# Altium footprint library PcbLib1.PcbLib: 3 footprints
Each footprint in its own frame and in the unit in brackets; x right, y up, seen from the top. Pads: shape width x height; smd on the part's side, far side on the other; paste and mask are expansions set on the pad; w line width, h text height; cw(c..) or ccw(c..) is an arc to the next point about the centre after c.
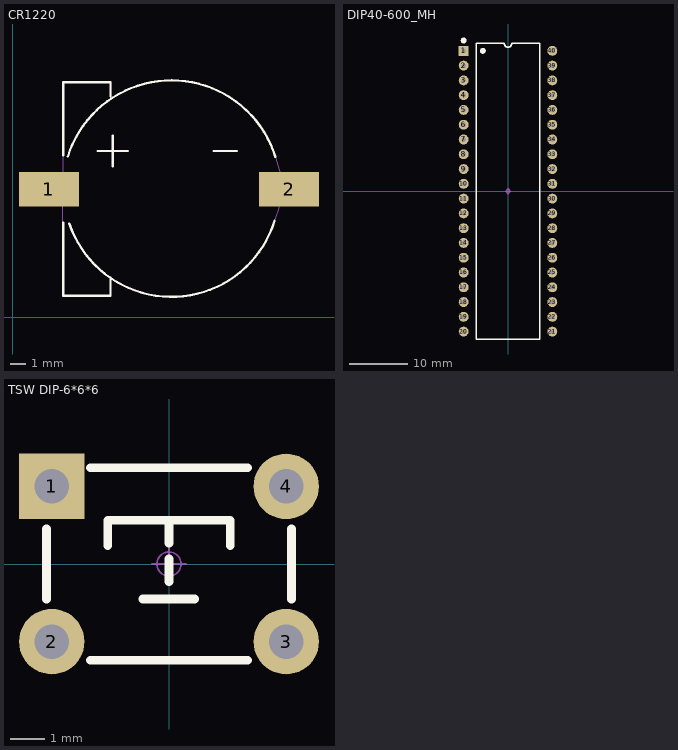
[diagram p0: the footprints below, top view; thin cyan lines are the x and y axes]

## CR1220 [mm] "纽扣电池"
pads (2):
  rect 4x2.3 smd paste+0 mask+0.05: 1(2.413,8.509) 2(18.415,8.509)
Top Overlay:
  lines w0.15: 3.361,6.305 3.361,1.424 6.517,1.424 6.517,2.624 ; 3.361,10.767 3.361,15.648 6.517,15.648 6.517,14.707 ; 3.67,10.711 cw(c10.581,8.536) 17.499,10.69 ; 3.766,6.239 ccw(c10.581,8.536) 17.452,6.412 ; 5.653,11.076 7.685,11.076 ; 6.669,10.06 6.669,12.092 ; 13.4,11.076 14.924,11.076
Mechanical 15:
  region: 0.561,9.436 3.961,9.436 3.961,7.636 0.561,7.636
  region: 19.901,7.636 16.501,7.636 16.501,9.436 19.901,9.436
  lines w0.051: 3.354,15.678 3.354,8.025 3.342,8.013 3.342,1.409 6.517,1.409 6.517,2.679 6.541,2.569 6.685,2.487 6.936,2.324 7.45,2.049 7.967,1.825 8.489,1.637 9.013,1.507 9.536,1.404 10.06,1.348 10.584,1.33 11.125,1.353 11.673,1.417 12.746,1.657 13.699,2.055 14.171,2.296 14.614,2.585 14.94,2.821 15.246,3.082 15.56,3.364 15.858,3.662 16.14,3.986 16.394,4.31 16.862,4.992 17.262,5.864 17.567,6.698 17.737,7.137 17.839,7.616 17.915,8.075 17.963,8.53 17.925,9.051 17.822,9.567 17.519,10.6 17.252,11.367 16.862,12.133 16.292,13.001 15.647,13.71 15.272,14.048 14.885,14.365 14.018,14.916 13.197,15.29 12.783,15.433 12.353,15.55 11.94,15.646 11.501,15.721 10.628,15.779 10.151,15.757 9.668,15.719 9.209,15.644 8.759,15.537 8.321,15.41 7.876,15.255 7.048,14.864 6.844,14.749 6.689,14.656 6.547,14.562 6.552,14.694 6.552,15.674 6.556,15.679 3.354,15.679 ; 3.354,15.678 3.354,15.679

## DIP40-600_MH [mm] "带底座 52*15.2*4mm(长宽高)"
pads (40):
  rect 1.7x1.7 hole 0.8: 1(-7.62,24.13)
  round 1.7 hole 0.8: 2(-7.62,21.59) 3(-7.62,19.05) 4(-7.62,16.51) 5(-7.62,13.97) 6(-7.62,11.43) 7(-7.62,8.89) 8(-7.62,6.35) 9(-7.62,3.81) 10(-7.62,1.27) 11(-7.62,-1.27) 12(-7.62,-3.81) 13(-7.62,-6.35) 14(-7.62,-8.89) 15(-7.62,-11.43) 16(-7.62,-13.97) 17(-7.62,-16.51) 18(-7.62,-19.05) 19(-7.62,-21.59) 20(-7.62,-24.13) 21(7.62,-24.13) 22(7.62,-21.59) 23(7.62,-19.05) 24(7.62,-16.51) 25(7.62,-13.97) 26(7.62,-11.43) 27(7.62,-8.89) 28(7.62,-6.35) 29(7.62,-3.81) 30(7.62,-1.27) 31(7.62,1.27) 32(7.62,3.81) 33(7.62,6.35) 34(7.62,8.89) 35(7.62,11.43) 36(7.62,13.97) 37(7.62,16.51) 38(7.62,19.05) 39(7.62,21.59) 40(7.62,24.13)
Top Overlay:
  circle w0.508: c-4.318,24.13 r0.254
  circle w0.508: c-7.62,25.908 r0.254
  lines w0.254: -5.461,-25.4 5.461,-25.4 5.461,25.4 0.635,25.4 cw(c0,25.4) -0.635,25.4 -5.461,25.4 -5.461,-25.4
Mechanical 15:
  circle w0.05: c0,0 r0.35
  lines w0.05: -0.5,0 0.5,0 ; 0,-0.5 0,0.5
3D body "DIP-MH40-600.STEP": height 5.2, standoff -3, extent -8.9,-25.3 8.9,25.3
3D body "DIP40-600.STEP": height 8.3, standoff 0.4, extent -7.78,-26.176 7.78,26.176

## TSW DIP-6*6*6 [mm] "6*6*6mm"
pads (4):
  rect 1.9x1.9 hole 1: 1(-3.4,2.25)
  round 1.9 hole 1: 2(-3.4,-2.25) 3(3.4,-2.25) 4(3.4,2.25)
Top Overlay:
  lines w0.254: -3.556,-1.016 -3.556,1.016 ; -2.286,-2.794 2.286,-2.794 ; -2.286,2.794 2.286,2.794 ; -1.778,0.533 -1.778,1.27 1.778,1.27 1.778,0.533 ; -0.762,-1.016 0.737,-1.016 ; 0,-0.508 0,0.152 ; 0,0.61 0,1.27 ; 3.556,-1.016 3.556,1.016
Bottom Overlay:
  lines w0.254: -2.286,-2.286 2.286,-2.286 ; -2.286,2.286 2.286,2.286
Mechanical 15:
  circle w0.05: c0,0 r0.35
  lines w0.05: -0.5,0 0.5,0 ; 0,-0.5 0,0.5
3D body "TSW DIP-6x6x6.STEP": height 5.95, standoff -3.45, extent -4.106,-3 4.106,3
